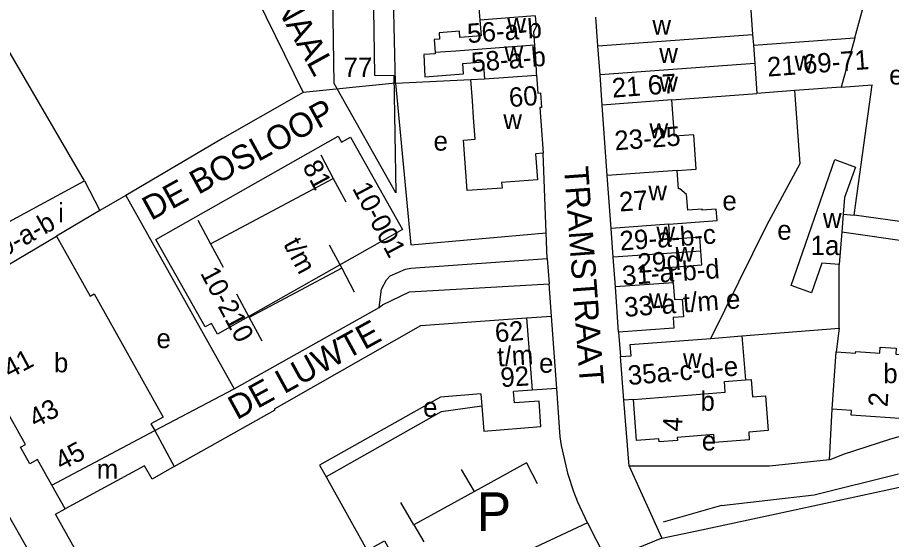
# Model space of a CAD drawing. Extents: x 160673 to 161924, y 382258 to 384145.
# Drawn here: x 161578.5 to 161759.3, y 383299.3 to 383407.2 of the extents above; entities that cross this region are included whole.
import ezdxf

# ---------------------------------------------------------------- set-up
doc = ezdxf.new("R2010")
doc.units = 0
for name, color, linetype in [('BLT_Basislijn', 7, 'Continuous'), ('BLT_Bebouwing', 7, 'Continuous'), ('BLT_Centroide', 7, 'Continuous'), ('BLT_Huisnummer', 7, 'Continuous'), ('BLT_Huisnummer_reeks', 7, 'Continuous'), ('BLT_Huisnummer_zonder_bebouwing', 7, 'Continuous'), ('BLT_Onderdoorgang_en_onderverdeling', 7, 'Continuous'), ('BLT_Onderverdeling_panden', 7, 'Continuous'), ('BLT_Plantopo', 7, 'Continuous'), ('BLT_Straatnaam', 7, 'Continuous'), ('BLT_Tekst_parkeren', 7, 'Continuous')]:
    doc.layers.add(name, color=color, linetype=linetype)

msp = doc.modelspace()

# ---------------------------------------------------------------- linework, layer by layer
at = {"layer": 'BLT_Basislijn'}
for p, q in [((161656.73, 383393.7), (161656.25, 383414.2)), ((161656.73, 383393.7), (161672.32, 383394.46)), ((161656.73, 383393.7), (161637.65, 383391.76)), ((161748.89, 383392.83), (161755.3, 383393.31)), ((161740.42, 383377.09), (161739.33, 383392.12)), ((161641.24, 383378.83), (161643.85, 383373.97)), ((161687.9, 383362.76), (161687.26, 383379.21)), ((161618.45, 383360.47), (161643.85, 383373.97)), ((161643.85, 383373.97), (161646.45, 383369.11)), ((161615.84, 383365.33), (161618.45, 383360.47)), ((161749.34, 383366.6), (161751.58, 383366.42)), ((161768.3, 383364.09), (161751.58, 383366.42)), ((161688.1, 383357.42), (161687.9, 383362.76)), ((161618.45, 383360.47), (161621.05, 383355.61)), ((161642.99, 383360.28), (161645.6, 383355.43)), ((161688.1, 383357.42), (161688.5, 383352.18)), ((161748.48, 383343.04), (161748.49, 383356.2)), ((161645.6, 383355.43), (161626.44, 383345.25)), ((161645.6, 383355.43), (161648.2, 383350.57)), ((161688.98, 383345.52), (161688.5, 383352.18)), ((161623.83, 383350.1), (161626.44, 383345.25)), ((161623.35, 383330.49), (161653.33, 383347.29)), ((161626.44, 383345.25), (161629.04, 383340.39)), ((161683.84, 383345.18), (161688.98, 383345.52)), ((161690.07, 383330.59), (161688.98, 383345.52)), ((161702.88, 383342.2), (161703.27, 383337.16)), ((161748.48, 383343.04), (161747.91, 383338.11)), ((161606.9, 383321.86), (161623.35, 383330.49)), ((161690.07, 383330.59), (161685.01, 383330.22)), ((161705.09, 383314.49), (161703.94, 383328.15)), ((161746.52, 383315.82), (161747.07, 383326.28)), ((161683.83, 383315.16), (161673.03, 383309.25)), ((161683.83, 383315.16), (161686.04, 383310.91)), ((161734.11, 383314.5), (161705.09, 383314.49)), ((161705.09, 383314.49), (161711.82, 383299.61)), ((161746.52, 383315.82), (161734.11, 383314.5)), ((161673.03, 383309.25), (161670.4, 383313.8)), ((161673.03, 383309.25), (161660.54, 383302.41)), ((161735.45, 383304.68), (161760.99, 383310.16)), ((161660.54, 383302.41), (161657.82, 383307)), ((161724.18, 383306.34), (161712.07, 383302.95)), ((161719.04, 383301.16), (161735.45, 383304.68)), ((161660.54, 383302.41), (161662.58, 383298.84)), ((161696.43, 383302.76), (161668.39, 383289.75)), ((161696.43, 383302.76), (161700.09, 383295.65)), ((161711.82, 383299.61), (161719.04, 383301.16)), ((161711.82, 383299.61), (161700.42, 383295.01))]:
    msp.add_line(p, q, dxfattribs=at)
for points in [[(161751.76, 383403.06), (161756.44, 383420.27), (161759.83, 383419.35), (161760.67, 383422.31), (161760.91, 383445.86)], [(161656.73, 383393.7), (161659.9, 383360.24), (161687.9, 383362.76)], [(161751.58, 383366.42), (161755.3, 383393.31)], [(161721.96, 383340.88), (161733.53, 383364.33), (161740.42, 383377.09)], [(161600.9, 383370.42), (161623.35, 383330.49)], [(161749.04, 383362.95), (161778.36, 383358.76), (161777.91, 383355.7), (161774.02, 383355.88), (161772.83, 383348.49), (161772.64, 383345.85), (161776.77, 383345.22), (161776.81, 383345.06), (161773.87, 383324.47), (161773.55, 383324.15), (161759.14, 383320.1), (161749.36, 383316.93), (161746.78, 383315.85), (161746.52, 383315.82)], [(161653.33, 383347.29), (161653.8, 383351.11), (161654.83, 383352.99), (161655.63, 383353.82), (161658.76, 383355.2), (161659.87, 383355.41), (161688.1, 383357.42)], [(161653.33, 383347.29), (161654.05, 383347.82), (161659.61, 383350.51), (161688.5, 383352.18)], [(161551.92, 383347.93), (161559.95, 383333.68), (161564.02, 383326.44), (161607.72, 383249.64), (161611.72, 383242.87)], [(161728.39, 383341.42), (161748.48, 383343.04)], [(161696.43, 383302.76), (161694.42, 383307.04), (161693.63, 383309.17), (161692.41, 383312.8), (161691.09, 383318.8), (161690.79, 383320.58), (161690.07, 383330.59)], [(161674.56, 383326.88), (161666.15, 383325.71), (161642.35, 383312.28)], [(161724.18, 383306.34), (161743.3, 383308.59), (161760.8, 383312.91)]]:
    msp.add_lwpolyline(points, dxfattribs=at)
at = {"layer": 'BLT_Bebouwing'}
for p, q in [((161619.3, 383429.06), (161637.65, 383391.76)), ((161730.15, 383409.7), (161730.59, 383403.73)), ((161698.59, 383401.37), (161698.15, 383407.34)), ((161730.59, 383403.73), (161730.76, 383401.52)), ((161699.03, 383395.4), (161698.59, 383401.37)), ((161730.76, 383401.52), (161751.76, 383403.06)), ((161751.76, 383403.06), (161748.89, 383392.83)), ((161672.32, 383394.46), (161675.11, 383394.58)), ((161699.49, 383389.09), (161699.03, 383395.4)), ((161748.89, 383392.83), (161739.33, 383392.12)), ((161713.9, 383390.22), (161731.49, 383391.53)), ((161739.33, 383392.12), (161731.49, 383391.53)), ((161700.54, 383374.58), (161699.49, 383389.09)), ((161687.26, 383379.21), (161685.69, 383379.09)), ((161701.33, 383363.64), (161700.54, 383374.58)), ((161714.96, 383375.59), (161718.95, 383375.89)), ((161600.9, 383370.42), (161595.57, 383367.37)), ((161595.57, 383367.37), (161586.58, 383362.02)), ((161701.76, 383357.7), (161701.33, 383363.64)), ((161702.2, 383351.57), (161701.76, 383357.7)), ((161702.88, 383342.2), (161702.2, 383351.57)), ((161683.84, 383345.18), (161685.01, 383330.22)), ((161703.94, 383328.15), (161703.27, 383337.16)), ((161685.01, 383330.22), (161681.13, 383329.91)), ((161705.93, 383328.3), (161703.94, 383328.15)), ((161640.99, 383314.71), (161642.35, 383312.28)), ((161588.37, 383305.7), (161585.65, 383310.6))]:
    msp.add_line(p, q, dxfattribs=at)
for points in [[(161666, 383412.28), (161666.21, 383409.47), (161673.91, 383410.05), (161674.17, 383406.71)], [(161674.17, 383406.71), (161674.42, 383403.42), (161670.05, 383403.09), (161669.95, 383404.42), (161665.73, 383404.1), (161665.83, 383402.77), (161664.69, 383402.68), (161664.9, 383399.98)], [(161685.62, 383407.62), (161685.79, 383405.34), (161685.29, 383404.29), (161685.49, 383401.55)], [(161592.4, 383373.5), (161573.77, 383405.34), (161557.21, 383395.54), (161554.39, 383400.56)], [(161685.49, 383401.55), (161685.7, 383398.81), (161685.81, 383396.19), (161685.85, 383395.64), (161685.86, 383395.3)], [(161664.9, 383399.98), (161664.91, 383399.75), (161662.55, 383399.61)], [(161662.55, 383399.61), (161662.8, 383395), (161670.79, 383395.63), (161670.62, 383397.76), (161674.85, 383398.08), (161675.11, 383394.58)], [(161673.18, 383382.08), (161672.84, 383386.6), (161672.65, 383390.02), (161672.32, 383394.46)], [(161685.86, 383395.3), (161686.14, 383391.62), (161686.69, 383391.66), (161686.9, 383388.65), (161686.55, 383388.62), (161687.26, 383379.21)], [(161637.65, 383391.76), (161620.96, 383382.24), (161600.9, 383370.42)], [(161718.95, 383375.89), (161718.41, 383383.01), (161714.46, 383382.72), (161713.9, 383390.22)], [(161685.69, 383379.09), (161686.1, 383373.68), (161678.68, 383373.11), (161678.76, 383372), (161671.57, 383371.46), (161670.78, 383381.9), (161673.18, 383382.08)], [(161738.54, 383351.86), (161747.59, 383377.88), (161751.88, 383376.33), (161749.62, 383370.04), (161749.34, 383366.6)], [(161713.27, 383364.53), (161723.26, 383365.27), (161723.09, 383367.64), (161720.16, 383367.42), (161720.15, 383367.62), (161717.18, 383367.4), (161716.93, 383370.66), (161715.56, 383371.84), (161715.24, 383371.82), (161714.96, 383375.59)], [(161567.27, 383359.8), (161570.66, 383361.62), (161570.06, 383362.78), (161572.07, 383363.84), (161572.6, 383362.79), (161592.4, 383373.5)], [(161749.34, 383366.6), (161749.04, 383362.95)], [(161719.89, 383358.97), (161719.67, 383361.85), (161713.5, 383361.39), (161713.27, 383364.53)], [(161586.58, 383362.02), (161593.52, 383349.65), (161594.36, 383350.12), (161608.66, 383324.65), (161606.13, 383323.23), (161606.9, 383321.86)], [(161749.04, 383362.95), (161748.49, 383356.2)], [(161713.91, 383355.64), (161720.1, 383356.1), (161719.89, 383358.97)], [(161748.49, 383356.2), (161744.93, 383356.47), (161742.8, 383350.33), (161738.54, 383351.86)], [(161714.15, 383352.43), (161713.91, 383355.64)], [(161714.15, 383352.43), (161714.42, 383348.92), (161716.05, 383349.04), (161716.32, 383345.37), (161714.15, 383345.2), (161714.31, 383343.05), (161702.88, 383342.2)], [(161585.65, 383310.6), (161582.67, 383315.9), (161581.09, 383315), (161579.13, 383318.43), (161580.16, 383319.01), (161566.25, 383343.82)], [(161633.77, 383327.56), (161661.95, 383343.58), (161683.84, 383345.18)], [(161703.27, 383337.16), (161705.46, 383337.32), (161705.28, 383339.64), (161721.96, 383340.88)], [(161721.96, 383340.88), (161728.39, 383341.42)], [(161728.39, 383341.42), (161729.12, 383332.37)], [(161747.91, 383338.11), (161751.9, 383337.85), (161751.92, 383338.2), (161756.91, 383337.88), (161756.99, 383339.13), (161760.32, 383338.92), (161760.24, 383337.67), (161763.97, 383337.43), (161763.94, 383337.08), (161768.15, 383336.81), (161767.38, 383324.85), (161763.13, 383325.12), (161763.07, 383324.19), (161750.97, 383325.05), (161751.04, 383325.99), (161747.07, 383326.28)], [(161747.07, 383326.28), (161747.49, 383332.19), (161747.91, 383338.11)], [(161729.12, 383332.37), (161730.28, 383332.45), (161730.55, 383328.81), (161733.29, 383329.01), (161733.81, 383321.85)], [(161674.36, 383329.43), (161666, 383328.77), (161640.99, 383314.71)], [(161674.36, 383329.43), (161674.56, 383326.88)], [(161674.56, 383326.88), (161674.96, 383321.75), (161686.81, 383322.68), (161686.43, 383327.96), (161681.33, 383327.59), (161681.13, 383329.91)], [(161610.92, 383314.41), (161631.83, 383326.13), (161631.7, 383326.38), (161633.77, 383327.56)], [(161733.81, 383321.85), (161729.79, 383321.56), (161729.91, 383319.92), (161722.69, 383319.38), (161722.57, 383321.02), (161715.02, 383320.46), (161715.07, 383319.8), (161711.27, 383319.5), (161711.21, 383320.16), (161706.58, 383319.82), (161705.93, 383328.3)], [(161606.9, 383321.86), (161610.92, 383314.41)], [(161642.35, 383312.28), (161650.89, 383297.09), (161654.42, 383299.07), (161664.48, 383281.17)], [(161640.6, 383266.93), (161617.24, 383253.87), (161609, 383268.61), (161604.67, 383266.17), (161590.52, 383291.38), (161592.99, 383292.77), (161592.27, 383294.05), (161591.88, 383293.89), (161591.41, 383293.86), (161590.95, 383294.03), (161590.53, 383294.36), (161590.28, 383294.83), (161590.22, 383295.34), (161590.3, 383295.77), (161590.47, 383296.19), (161590.93, 383296.45), (161586.36, 383304.56), (161588.37, 383305.7)]]:
    msp.add_lwpolyline(points, dxfattribs=at)
at = {"layer": 'BLT_Onderdoorgang_en_onderverdeling'}
msp.add_line((161585.65, 383310.6), (161606.9, 383321.86), dxfattribs=at)
msp.add_lwpolyline([(161610.92, 383314.41), (161606.37, 383311.84), (161604.81, 383314.6), (161588.37, 383305.7)], dxfattribs=at)
at = {"layer": 'BLT_Onderverdeling_panden'}
for p, q in [((161685.62, 383407.62), (161674.17, 383406.71)), ((161698.59, 383401.37), (161730.59, 383403.73)), ((161730.76, 383401.52), (161731.03, 383397.75)), ((161731.03, 383397.75), (161699.03, 383395.4)), ((161731.03, 383397.75), (161731.49, 383391.53)), ((161675.11, 383394.58), (161685.86, 383395.3)), ((161713.9, 383390.22), (161699.49, 383389.09)), ((161714.96, 383375.59), (161700.54, 383374.58)), ((161592.4, 383373.5), (161595.57, 383367.37)), ((161713.27, 383364.53), (161701.33, 383363.64)), ((161573.05, 383354.01), (161586.58, 383362.02)), ((161719.89, 383358.97), (161701.76, 383357.7)), ((161714.15, 383352.43), (161702.2, 383351.57))]:
    msp.add_line(p, q, dxfattribs=at)
for points in [[(161685.49, 383401.55), (161669.21, 383400.28), (161664.9, 383399.98)], [(161705.93, 383328.3), (161724.93, 383329.83), (161724.77, 383331.99), (161729.12, 383332.37)]]:
    msp.add_lwpolyline(points, dxfattribs=at)
at = {"layer": 'BLT_Plantopo'}
for points in [[(161656.79, 383370.98), (161644.03, 383393.63), (161642.09, 383520.78), (161642.13, 383522.83), (161613.73, 383522.01), (161614.87, 383445.65), (161593.83, 383483.47), (161592.91, 383526.64), (161598.84, 383531.12), (161650.29, 383532.45), (161652.34, 383395.31), (161656.34, 383395.28)], [(161607.12, 383361.39), (161644.86, 383382.71), (161645.56, 383381.47), (161647.41, 383382.51), (161658.18, 383363.43), (161619.89, 383341.81), (161618.64, 383344.02), (161617.34, 383343.29)]]:
    msp.add_lwpolyline(points, close=True, dxfattribs=at)

# ---------------------------------------------------------------- texts
at = {"layer": 'BLT_Centroide'}
for s, p in [('w', (161679.83, 383404.06)), ('w', (161709.86, 383403.68)), ('w', (161679.26, 383398.19)), ('w', (161711.28, 383397.87)), ('w', (161739.27, 383396.27)), ('e', (161758.84, 383393.38)), ('w', (161711.28, 383391.94)), ('w', (161679.02, 383384.17)), ('w', (161709.26, 383382.28)), ('e', (161664.59, 383379.72)), ('w', (161709.02, 383369.44)), ('i', (161586.92, 383364.88)), ('e', (161724.34, 383367.39)), ('w', (161745.14, 383363.73)), ('w', (161710.7, 383360.91)), ('e', (161735.7, 383361.31)), ('w', (161714.66, 383356.76)), ('w', (161709.14, 383347.16)), ('e', (161607.27, 383338.91)), ('b', (161586.05, 383333.9)), ('e', (161686.42, 383333.82)), ('w', (161716.19, 383334.78)), ('b', (161757.63, 383331.66)), ('b', (161719.81, 383325.97)), ('e', (161662.43, 383324.7)), ('e', (161720.08, 383317.75)), ('m', (161594.91, 383311.9))]:
    msp.add_text(s, height=4, dxfattribs=at).set_placement(p)
at = {"layer": 'BLT_Huisnummer'}
for s, rotation, p in [('60', 4.3218, (161680.32, 383388.71)), ('27', 4.269, (161703.13, 383367.13)), ('2', 86.7439, (161758.51, 383326.68)), ('4', 86.7439, (161715.97, 383321.61))]:
    msp.add_text(s, height=4, rotation=rotation, dxfattribs=at).set_placement(p)
msp.add_text('1a', height=4, dxfattribs=at).set_placement((161742.6, 383358.14))
at = {"layer": 'BLT_Huisnummer_reeks'}
for s, rotation, p in [('56-a-b', 4.3222, (161671.7, 383401.94)), ('58-a-b', 4.9617, (161672.55, 383395.94)), ('21 69-71', 4.2774, (161733.74, 383395.02)), ('77', 0.2663, (161645.98, 383394.95)), ('21 67', 4.2774, (161701.63, 383390.67)), ('23-25', 4.2785, (161702.16, 383379.78)), ('39-a-b', 29.3406, (161573.21, 383356.18)), ('29-a-b-c', 4.2709, (161703.24, 383359.06)), ('29d', 4.2759, (161706.96, 383354.44)), ('31-a-b-d', 4.2759, (161703.74, 383351.88)), ('33-a t/m e', 4.2774, (161704.17, 383345.36)), ('62', 5.0073, (161677.45, 383340.08)), ('41', 27.9572, (161576.93, 383332.56)), ('t/m', 3.7255, (161677.9, 383335.09)), ('35a-c-d-e', 5.0104, (161704.94, 383331.26)), ('92', 3.6452, (161678.55, 383330.83)), ('43', 27.9572, (161582.23, 383322.33)), ('45', 27.9572, (161587.63, 383313.5))]:
    msp.add_text(s, height=4, rotation=rotation, dxfattribs=at).set_placement(p)
at = {"layer": 'BLT_Huisnummer_zonder_bebouwing'}
for s, p in [('81', (161637.38, 383376.45)), ('10-001', (161647.68, 383371.95)), ('t/m', (161633.42, 383360.44)), ('10-210', (161616.25, 383354.41))]:
    msp.add_text(s, height=4, rotation=297.9572, dxfattribs=at).set_placement(p)
at = {"layer": 'BLT_Straatnaam'}
for s, rotation, p in [('DE DIAGONAAL', 298.769, (161615.85, 383438.71)), ('DE BOSLOOP', 28.769, (161606.15, 383365.18)), ('TRAMSTRAAT', 274.1772, (161691.58, 383376.31)), ('DE LUWTE', 28.769, (161623.9, 383323.98))]:
    msp.add_text(s, height=5, rotation=rotation, dxfattribs=at).set_placement(p)
at = {"layer": 'BLT_Tekst_parkeren'}
msp.add_text('P', height=8, dxfattribs=at).set_placement((161673.5, 383301.09))

doc.saveas('drawing.dxf')
